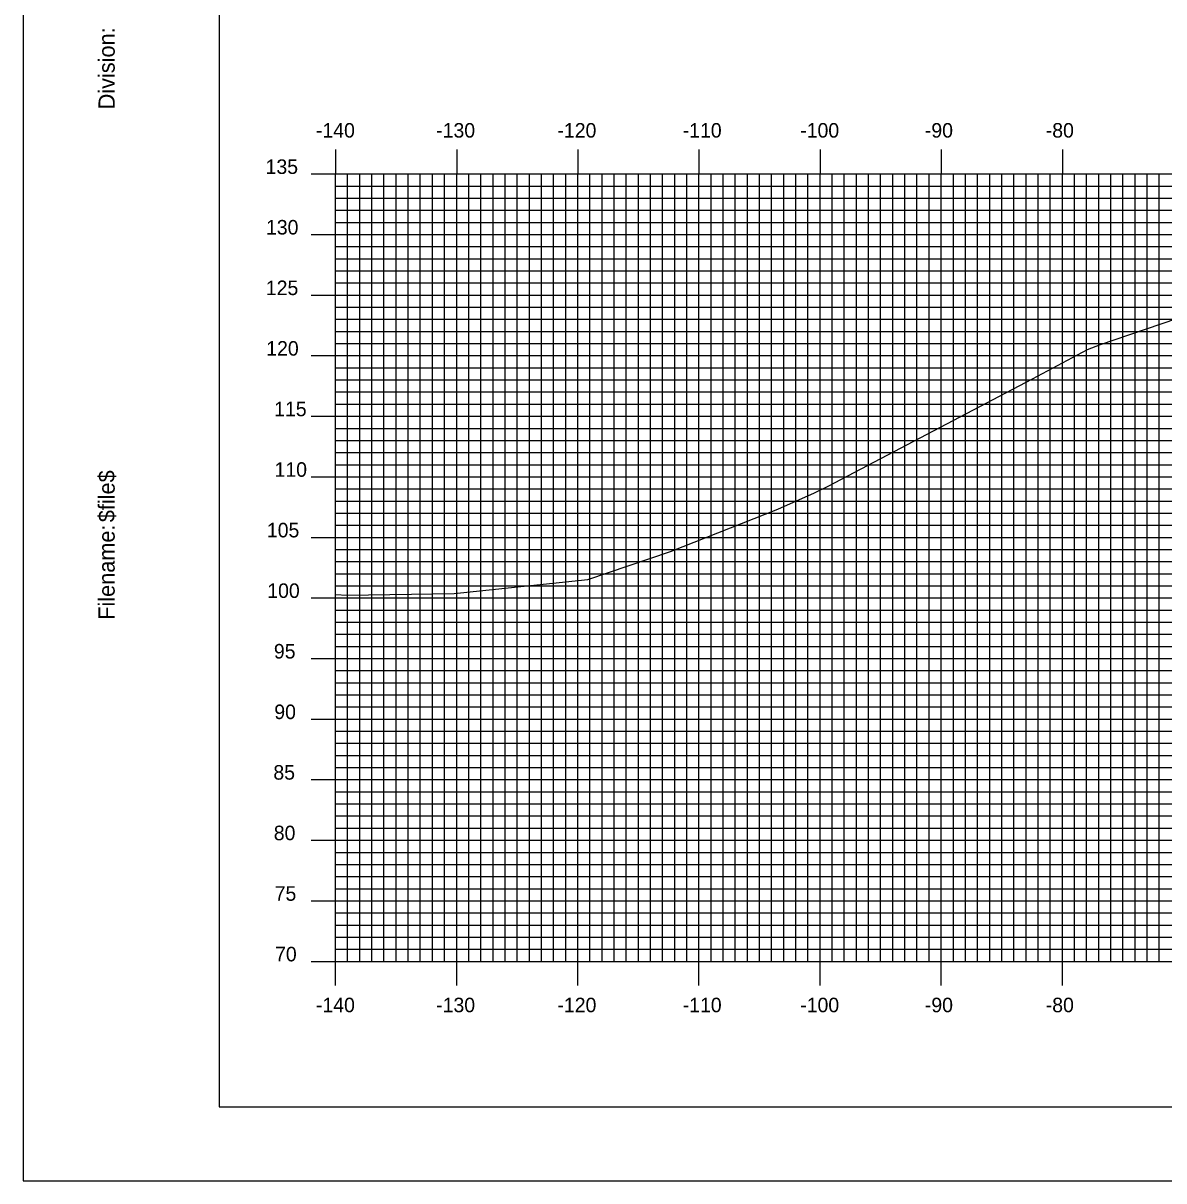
# Model space of a CAD drawing. Extents: x 859078 to 859421, y 364765 to 364985.
# Drawn here: x 859077.6 to 859171.7, y 364765.2 to 364860.7 of the extents above; entities that cross this region are included whole.
import ezdxf

# ---------------------------------------------------------------- set-up
doc = ezdxf.new("R2010")
doc.units = 0
for name, color, linetype in [('BORDER', 7, 'Continuous'), ('H_V ANNOTATION', 7, 'Continuous'), ('MAJOR', 7, 'Continuous'), ('MINOR', 7, 'Continuous'), ('PLOT BOUNDARY', 7, 'Continuous'), ('S_Roadway_Centerline', 7, 'Continuous')]:
    doc.layers.add(name, color=color, linetype=linetype)

msp = doc.modelspace()

# ---------------------------------------------------------------- linework, layer by layer
at = {"layer": 'BORDER'}
msp.add_lwpolyline([(859093.76, 364771.302), (859413.76, 364771.302), (859413.76, 364981.302), (859093.76, 364981.302)], close=True, dxfattribs=at)
at = {"layer": 'MAJOR'}
for p, q in [((859103.36, 364850.306), (859103.36, 364848.302)), ((859113.36, 364850.306), (859113.36, 364848.302)), ((859123.36, 364850.306), (859123.36, 364848.302)), ((859133.36, 364850.306), (859133.36, 364848.302)), ((859143.36, 364850.306), (859143.36, 364848.302)), ((859153.36, 364850.306), (859153.36, 364848.302)), ((859163.36, 364850.306), (859163.36, 364848.302)), ((859101.356, 364848.302), (859103.36, 364848.302)), ((859103.36, 364848.302), (859383.36, 364848.302)), ((859103.36, 364783.302), (859103.36, 364848.302)), ((859103.36, 364783.302), (859103.36, 364848.302)), ((859103.36, 364848.302), (859383.36, 364848.302)), ((859113.36, 364783.302), (859113.36, 364848.302)), ((859123.36, 364783.302), (859123.36, 364848.302)), ((859133.36, 364783.302), (859133.36, 364848.302)), ((859143.36, 364783.302), (859143.36, 364848.302)), ((859153.36, 364783.302), (859153.36, 364848.302)), ((859163.36, 364783.302), (859163.36, 364848.302)), ((859101.356, 364843.302), (859103.36, 364843.302)), ((859103.36, 364843.302), (859383.36, 364843.302)), ((859101.356, 364838.302), (859103.36, 364838.302)), ((859103.36, 364838.302), (859383.36, 364838.302)), ((859101.356, 364833.302), (859103.36, 364833.302)), ((859103.36, 364833.302), (859383.36, 364833.302)), ((859101.356, 364828.302), (859103.36, 364828.302)), ((859103.36, 364828.302), (859383.36, 364828.302)), ((859101.356, 364823.302), (859103.36, 364823.302)), ((859103.36, 364823.302), (859383.36, 364823.302)), ((859101.356, 364818.302), (859103.36, 364818.302)), ((859103.36, 364818.302), (859383.36, 364818.302)), ((859101.356, 364813.302), (859103.36, 364813.302)), ((859103.36, 364813.302), (859383.36, 364813.302)), ((859101.356, 364808.302), (859103.36, 364808.302)), ((859103.36, 364808.302), (859383.36, 364808.302)), ((859101.356, 364803.302), (859103.36, 364803.302)), ((859103.36, 364803.302), (859383.36, 364803.302)), ((859101.356, 364798.302), (859103.36, 364798.302)), ((859103.36, 364798.302), (859383.36, 364798.302)), ((859101.356, 364793.302), (859103.36, 364793.302)), ((859103.36, 364793.302), (859383.36, 364793.302)), ((859101.356, 364788.302), (859103.36, 364788.302)), ((859103.36, 364788.302), (859383.36, 364788.302)), ((859101.356, 364783.302), (859103.36, 364783.302)), ((859103.36, 364783.302), (859383.36, 364783.302)), ((859103.36, 364783.302), (859383.36, 364783.302)), ((859103.36, 364781.298), (859103.36, 364783.302)), ((859113.36, 364781.298), (859113.36, 364783.302)), ((859123.36, 364781.298), (859123.36, 364783.302)), ((859133.36, 364781.298), (859133.36, 364783.302)), ((859143.36, 364781.298), (859143.36, 364783.302)), ((859153.36, 364781.298), (859153.36, 364783.302)), ((859163.36, 364781.298), (859163.36, 364783.302))]:
    msp.add_line(p, q, dxfattribs=at)
at = {"layer": 'MINOR'}
for p, q in [((859104.36, 364783.302), (859104.36, 364848.302)), ((859105.36, 364783.302), (859105.36, 364848.302)), ((859106.36, 364783.302), (859106.36, 364848.302)), ((859107.36, 364783.302), (859107.36, 364848.302)), ((859108.36, 364783.302), (859108.36, 364848.302)), ((859109.36, 364783.302), (859109.36, 364848.302)), ((859110.36, 364783.302), (859110.36, 364848.302)), ((859111.36, 364783.302), (859111.36, 364848.302)), ((859112.36, 364783.302), (859112.36, 364848.302)), ((859114.36, 364783.302), (859114.36, 364848.302)), ((859115.36, 364783.302), (859115.36, 364848.302)), ((859116.36, 364783.302), (859116.36, 364848.302)), ((859117.36, 364783.302), (859117.36, 364848.302)), ((859118.36, 364783.302), (859118.36, 364848.302)), ((859119.36, 364783.302), (859119.36, 364848.302)), ((859120.36, 364783.302), (859120.36, 364848.302)), ((859121.36, 364783.302), (859121.36, 364848.302)), ((859122.36, 364783.302), (859122.36, 364848.302)), ((859124.36, 364783.302), (859124.36, 364848.302)), ((859125.36, 364783.302), (859125.36, 364848.302)), ((859126.36, 364783.302), (859126.36, 364848.302)), ((859127.36, 364783.302), (859127.36, 364848.302)), ((859128.36, 364783.302), (859128.36, 364848.302)), ((859129.36, 364783.302), (859129.36, 364848.302)), ((859130.36, 364783.302), (859130.36, 364848.302)), ((859131.36, 364783.302), (859131.36, 364848.302)), ((859132.36, 364783.302), (859132.36, 364848.302)), ((859134.36, 364783.302), (859134.36, 364848.302)), ((859135.36, 364783.302), (859135.36, 364848.302)), ((859136.36, 364783.302), (859136.36, 364848.302)), ((859137.36, 364783.302), (859137.36, 364848.302)), ((859138.36, 364783.302), (859138.36, 364848.302)), ((859139.36, 364783.302), (859139.36, 364848.302)), ((859140.36, 364783.302), (859140.36, 364848.302)), ((859141.36, 364783.302), (859141.36, 364848.302)), ((859142.36, 364783.302), (859142.36, 364848.302)), ((859144.36, 364783.302), (859144.36, 364848.302)), ((859145.36, 364783.302), (859145.36, 364848.302)), ((859146.36, 364783.302), (859146.36, 364848.302)), ((859147.36, 364783.302), (859147.36, 364848.302)), ((859148.36, 364783.302), (859148.36, 364848.302)), ((859149.36, 364783.302), (859149.36, 364848.302)), ((859150.36, 364783.302), (859150.36, 364848.302)), ((859151.36, 364783.302), (859151.36, 364848.302)), ((859152.36, 364783.302), (859152.36, 364848.302)), ((859154.36, 364783.302), (859154.36, 364848.302)), ((859155.36, 364783.302), (859155.36, 364848.302)), ((859156.36, 364783.302), (859156.36, 364848.302)), ((859157.36, 364783.302), (859157.36, 364848.302)), ((859158.36, 364783.302), (859158.36, 364848.302)), ((859159.36, 364783.302), (859159.36, 364848.302)), ((859160.36, 364783.302), (859160.36, 364848.302)), ((859161.36, 364783.302), (859161.36, 364848.302)), ((859162.36, 364783.302), (859162.36, 364848.302)), ((859164.36, 364783.302), (859164.36, 364848.302)), ((859165.36, 364783.302), (859165.36, 364848.302)), ((859166.36, 364783.302), (859166.36, 364848.302)), ((859167.36, 364783.302), (859167.36, 364848.302)), ((859168.36, 364783.302), (859168.36, 364848.302)), ((859169.36, 364783.302), (859169.36, 364848.302)), ((859170.36, 364783.302), (859170.36, 364848.302)), ((859171.36, 364783.302), (859171.36, 364848.302)), ((859103.36, 364847.302), (859383.36, 364847.302)), ((859103.36, 364847.302), (859105.364, 364847.302)), ((859103.36, 364846.302), (859383.36, 364846.302)), ((859103.36, 364846.302), (859105.364, 364846.302)), ((859103.36, 364845.302), (859383.36, 364845.302)), ((859103.36, 364845.302), (859105.364, 364845.302)), ((859103.36, 364844.302), (859383.36, 364844.302)), ((859103.36, 364844.302), (859105.364, 364844.302)), ((859103.36, 364842.302), (859383.36, 364842.302)), ((859103.36, 364842.302), (859105.364, 364842.302)), ((859103.36, 364841.302), (859383.36, 364841.302)), ((859103.36, 364841.302), (859105.364, 364841.302)), ((859103.36, 364840.302), (859383.36, 364840.302)), ((859103.36, 364840.302), (859105.364, 364840.302)), ((859103.36, 364839.302), (859383.36, 364839.302)), ((859103.36, 364839.302), (859105.364, 364839.302)), ((859103.36, 364837.302), (859383.36, 364837.302)), ((859103.36, 364837.302), (859105.364, 364837.302)), ((859103.36, 364836.302), (859383.36, 364836.302)), ((859103.36, 364836.302), (859105.364, 364836.302)), ((859103.36, 364835.302), (859383.36, 364835.302)), ((859103.36, 364835.302), (859105.364, 364835.302)), ((859103.36, 364834.302), (859383.36, 364834.302)), ((859103.36, 364834.302), (859105.364, 364834.302)), ((859103.36, 364832.302), (859383.36, 364832.302)), ((859103.36, 364832.302), (859105.364, 364832.302)), ((859103.36, 364831.302), (859383.36, 364831.302)), ((859103.36, 364831.302), (859105.364, 364831.302)), ((859103.36, 364830.302), (859383.36, 364830.302)), ((859103.36, 364830.302), (859105.364, 364830.302)), ((859103.36, 364829.302), (859383.36, 364829.302)), ((859103.36, 364829.302), (859105.364, 364829.302)), ((859103.36, 364827.302), (859383.36, 364827.302)), ((859103.36, 364827.302), (859105.364, 364827.302)), ((859103.36, 364826.302), (859383.36, 364826.302)), ((859103.36, 364826.302), (859105.364, 364826.302)), ((859103.36, 364825.302), (859383.36, 364825.302)), ((859103.36, 364825.302), (859105.364, 364825.302)), ((859103.36, 364824.302), (859383.36, 364824.302)), ((859103.36, 364824.302), (859105.364, 364824.302)), ((859103.36, 364822.302), (859383.36, 364822.302)), ((859103.36, 364822.302), (859105.364, 364822.302)), ((859103.36, 364821.302), (859383.36, 364821.302)), ((859103.36, 364821.302), (859105.364, 364821.302)), ((859103.36, 364820.302), (859383.36, 364820.302)), ((859103.36, 364820.302), (859105.364, 364820.302)), ((859103.36, 364819.302), (859383.36, 364819.302)), ((859103.36, 364819.302), (859105.364, 364819.302)), ((859103.36, 364817.302), (859383.36, 364817.302)), ((859103.36, 364817.302), (859105.364, 364817.302)), ((859103.36, 364816.302), (859383.36, 364816.302)), ((859103.36, 364816.302), (859105.364, 364816.302)), ((859103.36, 364815.302), (859383.36, 364815.302)), ((859103.36, 364815.302), (859105.364, 364815.302)), ((859103.36, 364814.302), (859383.36, 364814.302)), ((859103.36, 364814.302), (859105.364, 364814.302)), ((859103.36, 364812.302), (859383.36, 364812.302)), ((859103.36, 364812.302), (859105.364, 364812.302)), ((859103.36, 364811.302), (859383.36, 364811.302)), ((859103.36, 364811.302), (859105.364, 364811.302)), ((859103.36, 364810.302), (859383.36, 364810.302)), ((859103.36, 364810.302), (859105.364, 364810.302)), ((859103.36, 364809.302), (859383.36, 364809.302)), ((859103.36, 364809.302), (859105.364, 364809.302)), ((859103.36, 364807.302), (859383.36, 364807.302)), ((859103.36, 364807.302), (859105.364, 364807.302)), ((859103.36, 364806.302), (859383.36, 364806.302)), ((859103.36, 364806.302), (859105.364, 364806.302)), ((859103.36, 364805.302), (859383.36, 364805.302)), ((859103.36, 364805.302), (859105.364, 364805.302)), ((859103.36, 364804.302), (859383.36, 364804.302)), ((859103.36, 364804.302), (859105.364, 364804.302)), ((859103.36, 364802.302), (859383.36, 364802.302)), ((859103.36, 364802.302), (859105.364, 364802.302)), ((859103.36, 364801.302), (859383.36, 364801.302)), ((859103.36, 364801.302), (859105.364, 364801.302)), ((859103.36, 364800.302), (859383.36, 364800.302)), ((859103.36, 364800.302), (859105.364, 364800.302)), ((859103.36, 364799.302), (859383.36, 364799.302)), ((859103.36, 364799.302), (859105.364, 364799.302)), ((859103.36, 364797.302), (859383.36, 364797.302)), ((859103.36, 364797.302), (859105.364, 364797.302)), ((859103.36, 364796.302), (859383.36, 364796.302)), ((859103.36, 364796.302), (859105.364, 364796.302)), ((859103.36, 364795.302), (859383.36, 364795.302)), ((859103.36, 364795.302), (859105.364, 364795.302)), ((859103.36, 364794.302), (859383.36, 364794.302)), ((859103.36, 364794.302), (859105.364, 364794.302)), ((859103.36, 364792.302), (859383.36, 364792.302)), ((859103.36, 364792.302), (859105.364, 364792.302)), ((859103.36, 364791.302), (859383.36, 364791.302)), ((859103.36, 364791.302), (859105.364, 364791.302)), ((859103.36, 364790.302), (859383.36, 364790.302)), ((859103.36, 364790.302), (859105.364, 364790.302)), ((859103.36, 364789.302), (859383.36, 364789.302)), ((859103.36, 364789.302), (859105.364, 364789.302)), ((859103.36, 364787.302), (859383.36, 364787.302)), ((859103.36, 364787.302), (859105.364, 364787.302)), ((859103.36, 364786.302), (859383.36, 364786.302)), ((859103.36, 364786.302), (859105.364, 364786.302)), ((859103.36, 364785.302), (859383.36, 364785.302)), ((859103.36, 364785.302), (859105.364, 364785.302)), ((859103.36, 364784.302), (859383.36, 364784.302)), ((859103.36, 364784.302), (859105.364, 364784.302))]:
    msp.add_line(p, q, dxfattribs=at)
at = {"layer": 'PLOT BOUNDARY'}
msp.add_lwpolyline([(859077.573, 364765.184), (859417.573, 364765.184), (859417.573, 364985.184), (859077.573, 364985.184)], close=True, dxfattribs=at)
at = {"layer": 'S_Roadway_Centerline'}
msp.add_lwpolyline([(859103.36, 364813.597), (859104.311, 364813.538), (859113.143, 364813.681), (859124.184, 364814.817), (859131.019, 364817.14), (859139.866, 364820.639), (859142.899, 364821.986), (859144.014, 364822.533), (859160.904, 364831.396), (859165.442, 364833.812), (859166.501, 364834.214), (859177.889, 364838.109), (859179.794, 364838.242), (859196.275, 364839.41), (859212.997, 364840.052), (859229.266, 364840.688), (859248.223, 364841.049), (859248.392, 364841.052), (859248.584, 364840.972), (859269.616, 364831.984)], dxfattribs=at)

# ---------------------------------------------------------------- texts
at = {"layer": 'BORDER'}
for s, p in [('Division:', (859085.13, 364853.634)), ('$file$', (859085.13, 364819.553)), ('Filename:', (859085.13, 364811.499))]:
    msp.add_text(s, height=1.3392, rotation=90, dxfattribs=at).set_placement(p)
at = {"layer": 'H_V ANNOTATION'}
for s, p in [('-140', (859101.744, 364851.302)), ('-130', (859111.669, 364851.302)), ('-120', (859121.68, 364851.302)), ('-110', (859132.022, 364851.302)), ('-100', (859141.722, 364851.302)), ('-90', (859152.011, 364851.302)), ('-80', (859161.99, 364851.302)), ('135', (859097.588, 364848.302)), ('130', (859097.62, 364843.302)), ('125', (859097.609, 364838.302)), ('120', (859097.641, 364833.302)), ('115', (859098.295, 364828.302)), ('110', (859098.327, 364823.302)), ('105', (859097.695, 364818.302)), ('100', (859097.727, 364813.302)), ('95', (859098.273, 364808.302)), ('90', (859098.305, 364803.302)), ('85', (859098.23, 364798.302)), ('80', (859098.262, 364793.302)), ('75', (859098.336, 364788.302)), ('70', (859098.368, 364783.302)), ('-140', (859101.744, 364779.102)), ('-130', (859111.669, 364779.102)), ('-120', (859121.68, 364779.102)), ('-110', (859132.022, 364779.102)), ('-100', (859141.722, 364779.102)), ('-90', (859152.011, 364779.102)), ('-80', (859161.99, 364779.102))]:
    msp.add_text(s, height=1.2, dxfattribs=at).set_placement(p)
at = {"layer": 'MAJOR'}
msp.add_text('-', height=0.012, dxfattribs=at).set_placement((859103.351, 364783.302))

doc.saveas('drawing.dxf')
